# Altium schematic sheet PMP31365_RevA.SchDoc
size A2; Date: Not shown in title block; ApprovedBy: Not shown in title block; CheckedBy: Not shown in title block; Author: Not shown in title block; CompanyName: Not shown in title block; Engineer: Not shown in title block; Organization: Not shown in title block; Address1: Not shown in title block; Address2: Not shown in title block; Address3: Not shown in title block; Address4: Not shown in title block; DocumentNumber: 2; Revision: Use project parameter SCH_Rev; SheetNumber: 1; SheetTotal: 1; PageSetup: Record=PageOptions¦CenterHorizontal=True¦CenterVertical=True¦PrintScale=1.00¦XCorrection=1.00¦YCorrection=1.00¦PrintKind=0¦BorderSize=5000000¦LeftOffset=0¦BottomOffset=0¦Orientation=2¦PaperLength=1000¦PaperWidth=1000¦Scale=100¦PaperSource=15¦PrintQuality=600¦MediaType=1¦DitherType=10¦PaperKind=Letter¦PrintScaleMode=1
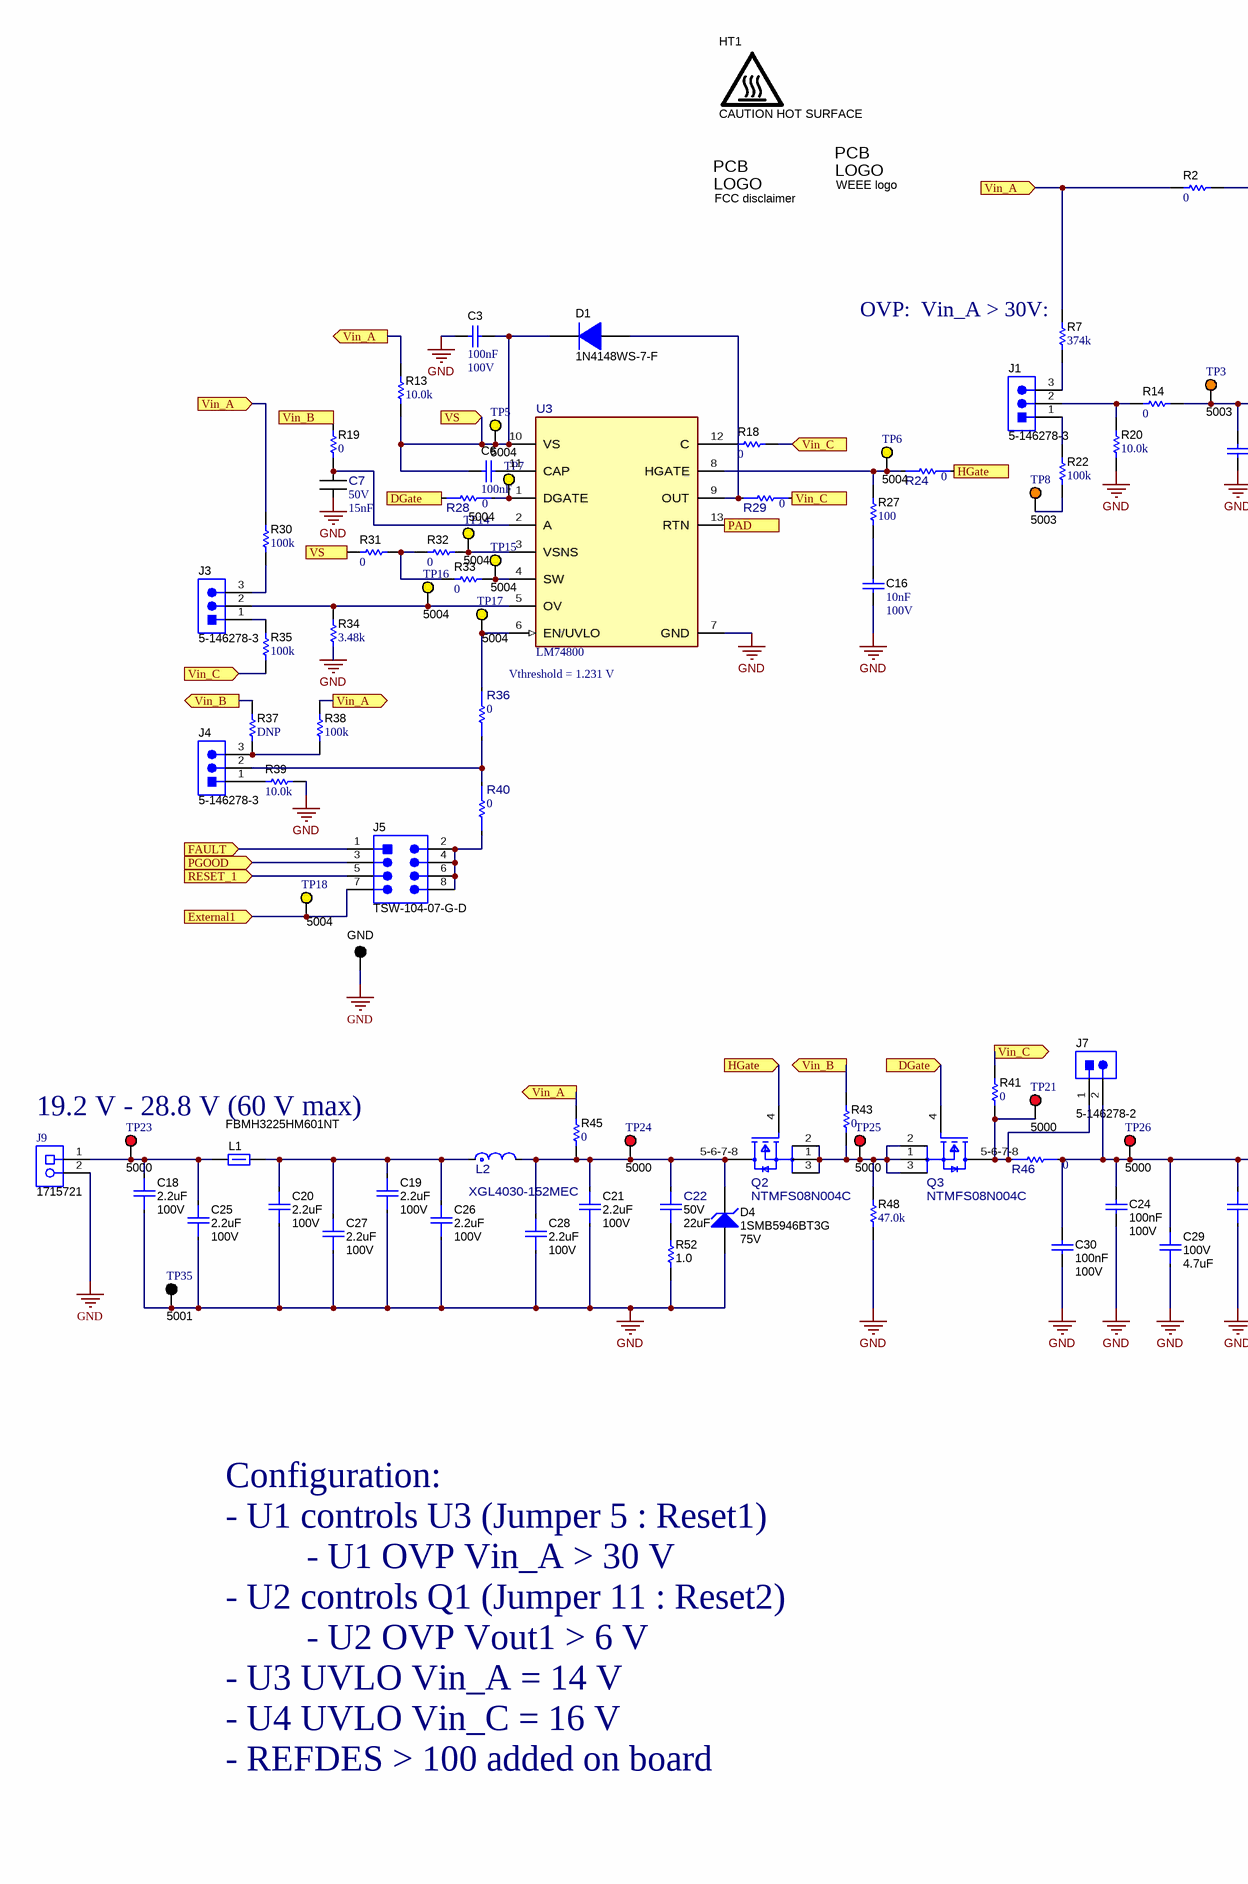
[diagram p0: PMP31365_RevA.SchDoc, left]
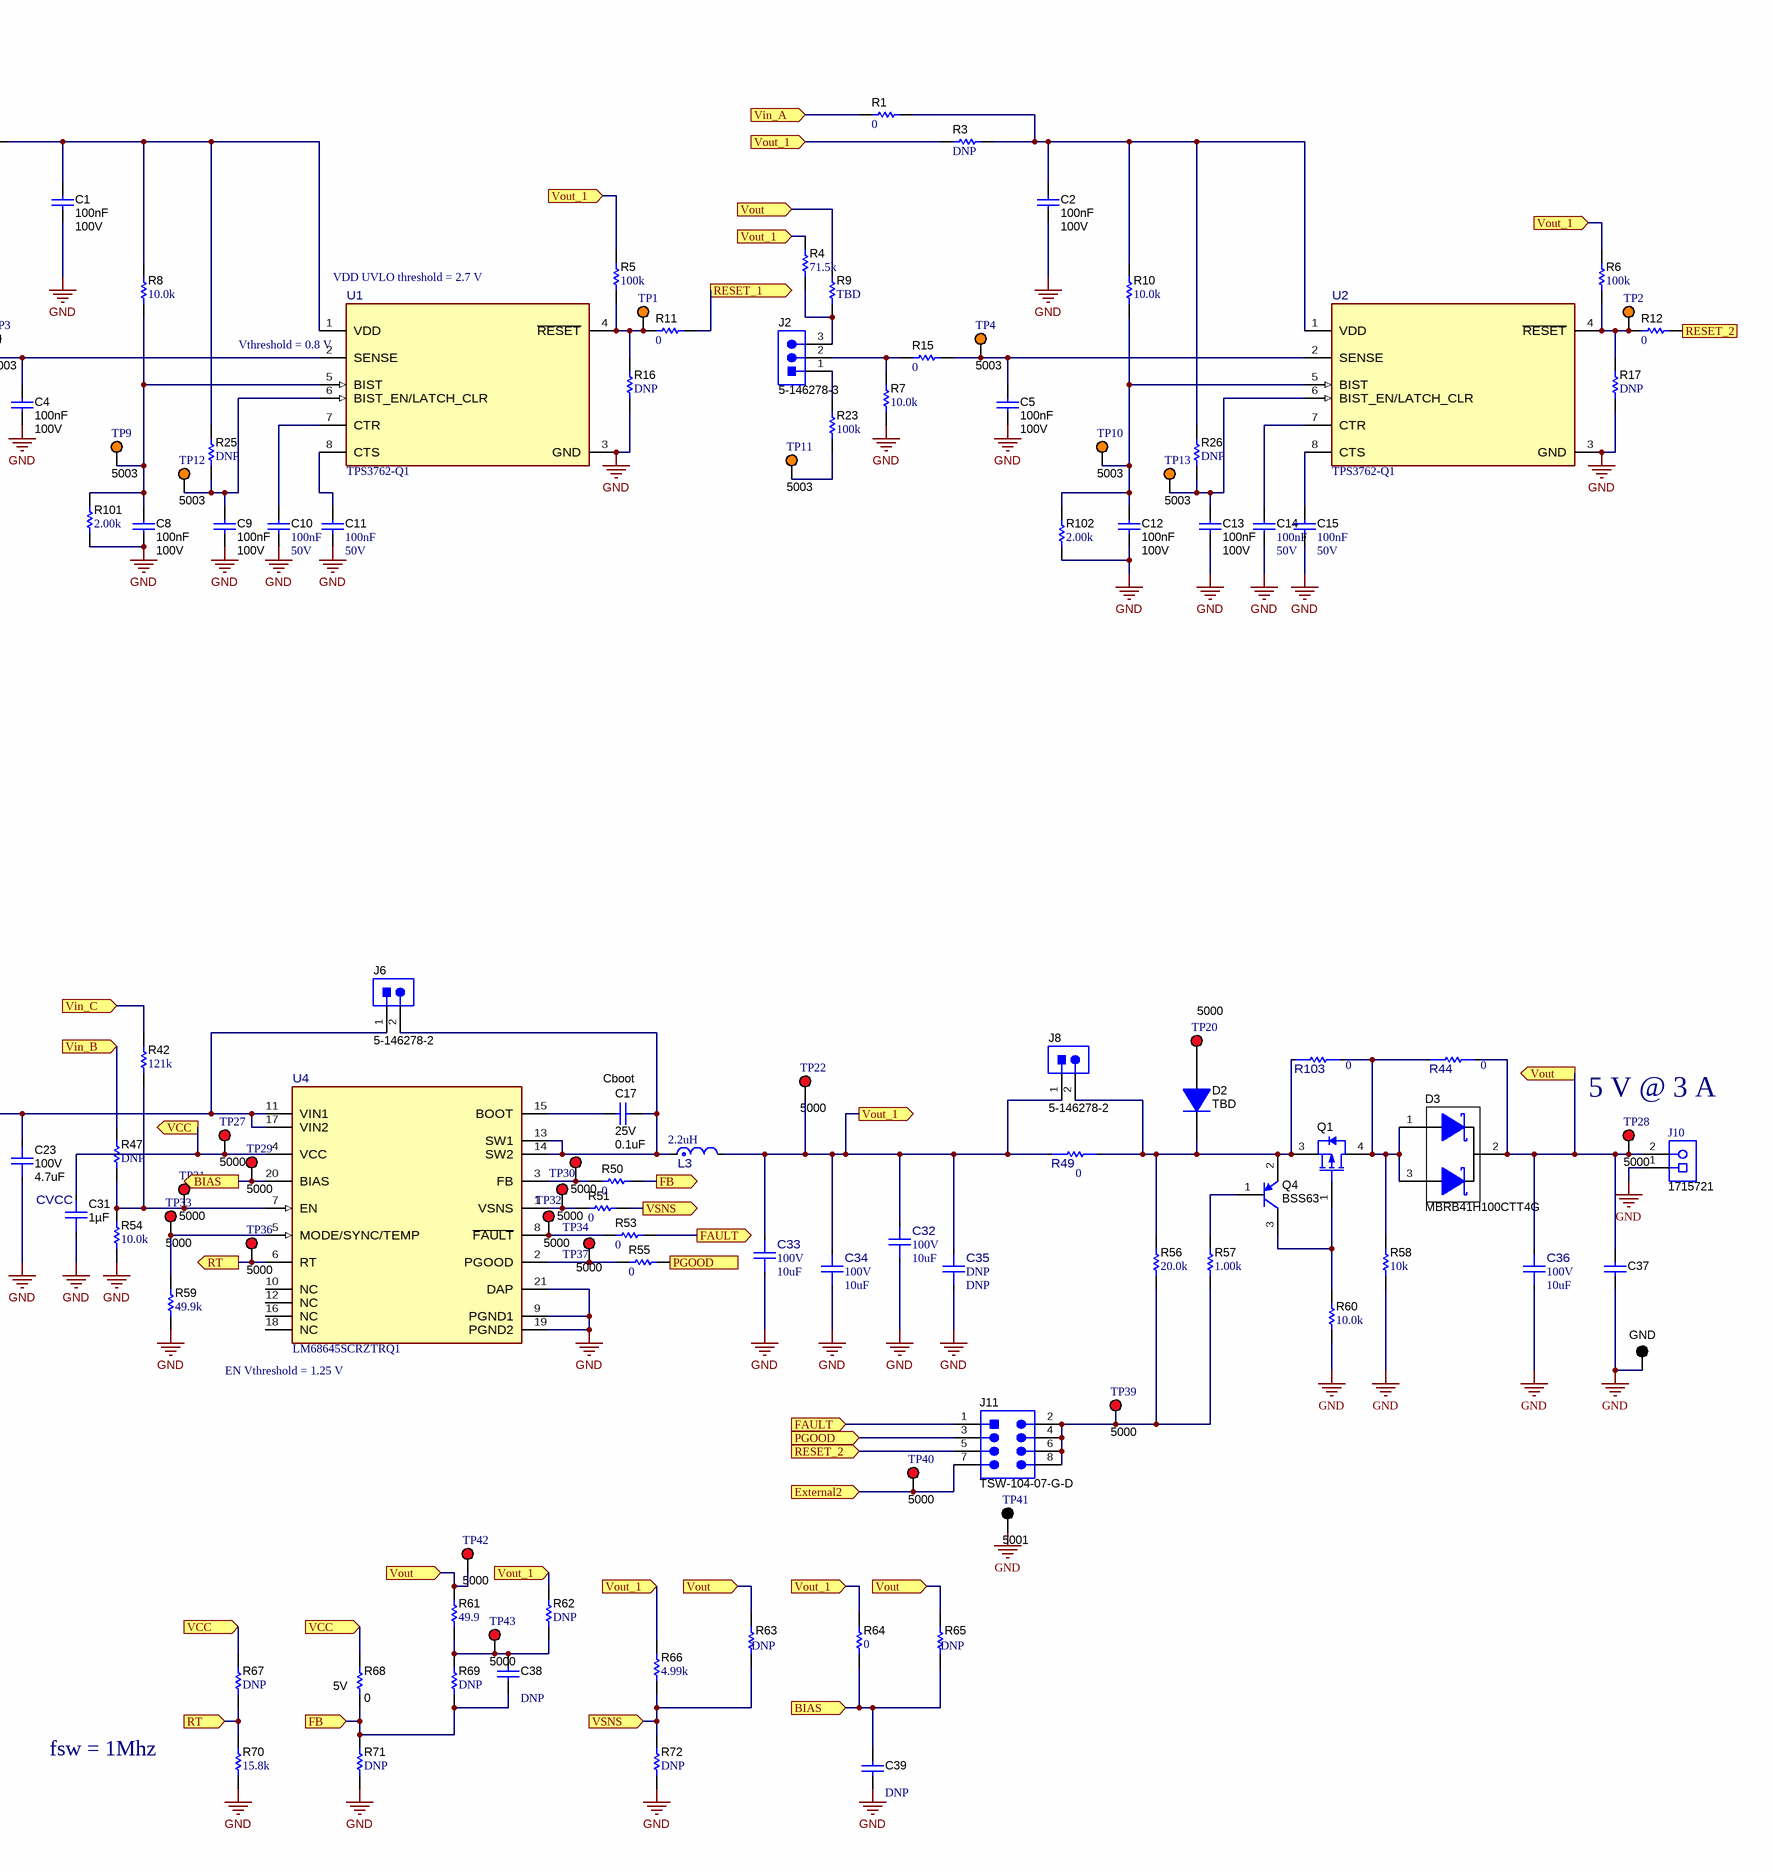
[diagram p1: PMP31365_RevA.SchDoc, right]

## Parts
(Parts that share a designator on the sheet are numbered #1, #2 ... from top to bottom, then left to right.)
1  FCC disclaimer  [FCC_disclaimer]  (no BOM)
C1  Cap_F: 100nF  VDC_V: 100V  [0603L]  (hidden comment: HMK107B7104KAHT)
C2  Cap_F: 100nF  VDC_V: 100V  [0603L]  (hidden comment: HMK107B7104KAHT)
C3  Cap_F: 100nF  VDC_V: 100V  [0603]  (hidden comment: GRM188R72A104KA35D)
C4  Cap_F: 100nF  VDC_V: 100V  [0603L]  (hidden comment: HMK107B7104KAHT)
C5  Cap_F: 100nF  VDC_V: 100V  [0603L]  (hidden comment: HMK107B7104KAHT)
C6  Cap_F: 100nF  [0603]  (hidden comment: 06035C104KAZ2A)
C7  VDC_V: 50V  Cap_F: 15nF  [FP-C0603C153K5RACTU_0603-MFG]  (hidden comment: C0603C153K5RACTU)
C8  Cap_F: 100nF  VDC_V: 100V  [0603L]  (hidden comment: HMK107B7104KAHT)
C9  Cap_F: 100nF  VDC_V: 100V  [0603L]  (hidden comment: HMK107B7104KAHT)
C10  Cap_F: 100nF  VDC_V: 50V  [0603]  (hidden comment: C0603C104K5RACTU)
C11  Cap_F: 100nF  VDC_V: 50V  [0603]  (hidden comment: C0603C104K5RACTU)
C12  Cap_F: 100nF  VDC_V: 100V  [0603L]  (hidden comment: HMK107B7104KAHT)
C13  Cap_F: 100nF  VDC_V: 100V  [0603L]  (hidden comment: HMK107B7104KAHT)
C14  Cap_F: 100nF  VDC_V: 50V  [0603]  (hidden comment: C0603C104K5RACTU)
C15  Cap_F: 100nF  VDC_V: 50V  [0603]  (hidden comment: C0603C104K5RACTU)
C16  Cap_F: 10nF  VDC_V: 100V  [0805_HV]  (hidden comment: 08051C103JAT2A)
C17  Cboot  VDC_V: 25V  ValueDisplayed: 0.1uF  [0402L]
C18  ValueDisplayed: 2.2uF  VDC_V: 100V  [FP-GRM21BD72A225ME01K_0805-IPC_C]  (hidden comment: GRM21BD72A225ME01K)
C19  ValueDisplayed: 2.2uF  VDC_V: 100V  [FP-GRM21BD72A225ME01K_0805-IPC_C]  (hidden comment: GRM21BD72A225ME01K)
C20  ValueDisplayed: 2.2uF  VDC_V: 100V  [FP-GRM21BD72A225ME01K_0805-IPC_C]  (hidden comment: GRM21BD72A225ME01K)
C21  ValueDisplayed: 2.2uF  VDC_V: 100V  [FP-GRM21BD72A225ME01K_0805-IPC_C]  (hidden comment: GRM21BD72A225ME01K)
C22  VDC_V: 50V  ValueDisplayed: 22uF  [FP-CGA9P3X7R1H226M250KB_2220-MFG]  (hidden comment: CGA9P3X7R1H226M250KB)
C23  VDC_V: 100V  ValueDisplayed: 4.7uF  [FP-GRM31CC72A475KE11L_1206-IPC_C]  (hidden comment: GRM31CC72A475KE11L)
C24  Cap_F: 100nF  VDC_V: 100V  [0603L]  (hidden comment: HMK107B7104KAHT)
C25  ValueDisplayed: 2.2uF  VDC_V: 100V  [FP-GRM21BD72A225ME01K_0805-IPC_C]  (hidden comment: GRM21BD72A225ME01K)
C26  ValueDisplayed: 2.2uF  VDC_V: 100V  [FP-GRM21BD72A225ME01K_0805-IPC_C]  (hidden comment: GRM21BD72A225ME01K)
C27  ValueDisplayed: 2.2uF  VDC_V: 100V  [FP-GRM21BD72A225ME01K_0805-IPC_C]  (hidden comment: GRM21BD72A225ME01K)
C28  ValueDisplayed: 2.2uF  VDC_V: 100V  [FP-GRM21BD72A225ME01K_0805-IPC_C]  (hidden comment: GRM21BD72A225ME01K)
C29  VDC_V: 100V  ValueDisplayed: 4.7uF  [FP-GRM31CC72A475KE11L_1206-IPC_C]  (hidden comment: GRM31CC72A475KE11L)
C30  Cap_F: 100nF  VDC_V: 100V  [0603L]  (hidden comment: HMK107B7104KAHT)
C31  CVCC  Cap_F: 1µF  [FP-CGA3E1X7R1C105M080AC_0603-IPC_C]
C32  VDC_V: 100V  ValueDisplayed: 10uF  [FP-C3225X7R2A106K250AC_1210-MFG]  (hidden comment: C3225X7R2A106K250AC)
C33  VDC_V: 100V  ValueDisplayed: 10uF  [FP-C3225X7R2A106K250AC_1210-MFG]  (hidden comment: C3225X7R2A106K250AC)
C34  VDC_V: 100V  ValueDisplayed: 10uF  [FP-C3225X7R2A106K250AC_1210-MFG]  (hidden comment: C3225X7R2A106K250AC)
C35  C3225X7R2A106K250AC  [FP-C3225X7R2A106K250AC_1210-MFG]  (value not drawn)
C36  VDC_V: 100V  ValueDisplayed: 10uF  [FP-C3225X7R2A106K250AC_1210-MFG]  (hidden comment: C3225X7R2A106K250AC)
C37  Used in BOM report  [1210]  (value not drawn)
C38  C0603C100J5GACTU  [0603]  (value not drawn)
C39  C0603C100J5GACTU  [0603]  (value not drawn)
D1  1N4148WS-7-F  [SOD-323]
D2  TBD  [SMA]
D3  MBRB41H100CTT4G  [DDPAK]
D4  1SMB5946BT3G  value 75V  [SMB]
HT1  CAUTION HOT SURFACE  [IEC_HotSurface_Medium]  (no BOM)
J1  5-146278-3  [TE_5-146278-3]
J2  5-146278-3  [TE_5-146278-3]
J3  5-146278-3  [TE_5-146278-3]
J4  5-146278-3  [TE_5-146278-3]
J5  TSW-104-07-G-D  [TSW-104-07-G-D]
J6  5-146278-2  [TE_5-146278-2]
J7  5-146278-2  [TE_5-146278-2]
J8  5-146278-2  [TE_5-146278-2]
J9  1715721  [PhoenixContact_1715721]
J10  1715721  [PhoenixContact_1715721]
J11  TSW-104-07-G-D  [TSW-104-07-G-D]
L1  FBMH3225HM601NT  [1210_280]
L2  XGL4030-152MEC  [FP-XGL4030-152MEC_SMT2_4MM0_4MM0-MFG]
L3  value 2.2uH  [FP-XGL6060-182MEC_SMT2_6MM51_6MM71-MFG]  (hidden comment: XGL6060-222MEC)
Q1  (no value)  [DPAK]
Q2  NTMFS08N004C  [FP-NTMFS08N004C_PQFN8-MFG]
Q3  NTMFS08N004C  [FP-NTMFS08N004C_PQFN8-MFG]
Q4  BSS63  [SOT-23]
R1  ValueDisplayed: 0  [0603]  (hidden comment: RMCF0603ZT0R00)
R2  ValueDisplayed: 0  [0603]  (hidden comment: RMCF0603ZT0R00)
R3  RMCF0603ZT0R00  [0603]  (value not drawn)
R4  ValueDisplayed: 71.5k  [0603]  (hidden comment: CRCW060371K5FKEA)
R5  ValueDisplayed: 100k  [0603]  (hidden comment: CRCW0603100KFKEA)
R6  ValueDisplayed: 100k  [0603]  (hidden comment: CRCW0603100KFKEA)
R7#1  ValueDisplayed: 374k  [0603]  (hidden comment: CRCW0603374KFKEA)
R7#2  ValueDisplayed: 10.0k  [0603]  (hidden comment: CRCW060310K0FKEA)
R8  ValueDisplayed: 10.0k  [0603]  (hidden comment: CRCW060310K0FKEA)
R9  ValueDisplayed: TBD  [0603]  (hidden comment: RMCF0603ZT0R00)
R10  ValueDisplayed: 10.0k  [0603]  (hidden comment: CRCW060310K0FKEA)
R11  ValueDisplayed: 0  [0603]  (hidden comment: RMCF0603ZT0R00)
R12  ValueDisplayed: 0  [0603]  (hidden comment: RMCF0603ZT0R00)
R13  ValueDisplayed: 10.0k  [0603]  (hidden comment: CRCW060310K0FKEA)
R14  ValueDisplayed: 0  [0603]  (hidden comment: RMCF0603ZT0R00)
R15  ValueDisplayed: 0  [0603]  (hidden comment: RMCF0603ZT0R00)
R16  RMCF0603ZT0R00  [0603]  (value not drawn)
R17  RMCF0603ZT0R00  [0603]  (value not drawn)
R18  ValueDisplayed: 0  [0603]  (hidden comment: RMCF0603ZT0R00)
R19  ValueDisplayed: 0  [0603]  (hidden comment: RMCF0603ZT0R00)
R20  ValueDisplayed: 10.0k  [0603]  (hidden comment: CRCW060310K0FKEA)
R22  ValueDisplayed: 100k  [0603]  (hidden comment: CRCW0603100KFKEA)
R23  ValueDisplayed: 100k  [0603]  (hidden comment: CRCW0603100KFKEA)
R24  Res_ohm: 0  [FP-RMCF0805ZT0R00_0805-MFG]  (hidden comment: RMCF0805ZT0R00)
R25  DNP  [0603]
R26  DNP  [0603]
R27  ValueDisplayed: 100  [0805_HV]  (hidden comment: CRCW0805100RFKEA)
R28  Res_ohm: 0  [FP-RMCF0805ZT0R00_0805-MFG]  (hidden comment: RMCF0805ZT0R00)
R29  Res_ohm: 0  [FP-RMCF0805ZT0R00_0805-MFG]  (hidden comment: RMCF0805ZT0R00)
R30  ValueDisplayed: 100k  [0603]  (hidden comment: CRCW0603100KFKEA)
R31  ValueDisplayed: 0  [0603]  (hidden comment: RMCF0603ZT0R00)
R32  ValueDisplayed: 0  [0603]  (hidden comment: RMCF0603ZT0R00)
R33  ValueDisplayed: 0  [0603]  (hidden comment: RMCF0603ZT0R00)
R34  ValueDisplayed: 3.48k  [0603]  (hidden comment: CRCW06033K48FKEA)
R35  ValueDisplayed: 100k  [0603]  (hidden comment: CRCW0603100KFKEA)
R36  Res_ohm: 0  [FP-RMCF0805ZT0R00_0805-MFG]  (hidden comment: RMCF0805ZT0R00)
R37  DNP  [0603]
R38  ValueDisplayed: 100k  [0603]  (hidden comment: CRCW0603100KFKEA)
R39  ValueDisplayed: 10.0k  [0603]  (hidden comment: CRCW060310K0FKEA)
R40  Res_ohm: 0  [FP-RMCF0805ZT0R00_0805-MFG]  (hidden comment: RMCF0805ZT0R00)
R41  ValueDisplayed: 0  [0603]  (hidden comment: RMCF0603ZT0R00)
R42  ValueDisplayed: 121k  [0603]  (hidden comment: CRCW0603121KFKEA)
R43  ValueDisplayed: 0  [0603]  (hidden comment: RMCF0603ZT0R00)
R44  value 0  [FP-CRCW12060000Z0EAC_1206-MFG]  (hidden comment: CRCW12060000Z0EAC)
R45  ValueDisplayed: 0  [0603]  (hidden comment: RMCF0603ZT0R00)
R46  value 0  [FP-CRCW12060000Z0EAC_1206-MFG]  (hidden comment: CRCW12060000Z0EAC)
R47  RMCF0603ZT0R00  [0603]  (value not drawn)
R48  ValueDisplayed: 47.0k  [1206]  (hidden comment: RC1206FR-0747KL)
R49  value 0  [FP-CRCW12060000Z0EAC_1206-MFG]  (hidden comment: CRCW12060000Z0EAC)
R50  ValueDisplayed: 0  [0603]  (hidden comment: RMCF0603ZT0R00)
R51  ValueDisplayed: 0  [0603]  (hidden comment: RMCF0603ZT0R00)
R52  ValueDisplayed: 1.0  [0805_HV]  (hidden comment: ESR10EZPJ1R0)
R53  ValueDisplayed: 0  [0603]  (hidden comment: RMCF0603ZT0R00)
R54  ValueDisplayed: 10.0k  [0603]  (hidden comment: CRCW060310K0FKEA)
R55  ValueDisplayed: 0  [0603]  (hidden comment: RMCF0603ZT0R00)
R56  ValueDisplayed: 20.0k  [0603]  (hidden comment: CRCW060320K0FKEA)
R57  ValueDisplayed: 1.00k  [0603]  (hidden comment: CRCW06031K00FKEA)
R58  ValueDisplayed: 10k  [1206]  (hidden comment: CRCW120610K0JNEA)
R59  ValueDisplayed: 49.9k  [0603]  (hidden comment: CRCW060349K9FKEA)
R60  ValueDisplayed: 10.0k  [0603]  (hidden comment: CRCW060310K0FKEA)
R61  ValueDisplayed: 49.9  [0603]  (hidden comment: M55342K12B49D9T)
R62  RMCF0603ZT0R00  [0603]  (value not drawn)
R63  RMCF0603ZT0R00  [0603]  (value not drawn)
R64  ValueDisplayed: 0  [0603]  (hidden comment: RMCF0603ZT0R00)
R65  RMCF0603ZT0R00  [0603]  (value not drawn)
R66  ValueDisplayed: 4.99k  [0603]  (hidden comment: CRCW06034K99FKEA)
R67  RMCF0603ZT0R00  [0603]  (value not drawn)
R68  5V  ValueDisplayed: 0  [0603L]
R69  RMCF0603ZT0R00  [0603]  (value not drawn)
R70  ValueDisplayed: 15.8k  [0603]  (hidden comment: CRCW060315K8FKEA)
R71  RMCF0603ZT0R00  [0603]  (value not drawn)
R72  RMCF0603ZT0R00  [0603]  (value not drawn)
R101  ValueDisplayed: 2.00k  [VSMP_0603]  (hidden comment: Y16362K00000F9R)
R102  ValueDisplayed: 2.00k  [VSMP_0603]  (hidden comment: Y16362K00000F9R)
R103  value 0  [FP-CRCW12060000Z0EAC_1206-MFG]  (hidden comment: CRCW12060000Z0EAC)
TP1  5003  [Keystone5003]  (value not drawn)
TP2  5003  [Keystone5003]  (value not drawn)
TP3  5003  [Keystone5003]
TP4  5003  [Keystone5003]
TP5  5004  [Keystone5004]
TP6  5004  [Keystone5004]
TP7  5004  [Keystone5004]
TP8  5003  [Keystone5003]
TP9  5003  [Keystone5003]
TP10  5003  [Keystone5003]
TP11  5003  [Keystone5003]
TP12  5003  [Keystone5003]
TP13  5003  [Keystone5003]
TP14  5004  [Keystone5004]
TP15  5004  [Keystone5004]
TP16  5004  [Keystone5004]
TP17  5004  [Keystone5004]
TP18  5004  [Keystone5004]
TP19  GND  [Keystone5011]
TP20  5000  [Keystone5000]
TP21  5000  [Keystone5000]
TP22  5000  [Keystone5000]
TP23  5000  [Keystone5000]
TP24  5000  [Keystone5000]
TP25  5000  [Keystone5000]
TP26  5000  [Keystone5000]
TP27  5000  [Keystone5000]
TP28  5000  [Keystone5000]
TP29  5000  [Keystone5000]
TP30  5000  [Keystone5000]
TP31  5000  [Keystone5000]
TP32  5000  [Keystone5000]
TP33  5000  [Keystone5000]
TP34  5000  [Keystone5000]
TP35  5001  [Keystone5001]
TP36  5000  [Keystone5000]
TP37  5000  [Keystone5000]
TP38  GND  [Keystone5011]
TP39  5000  [Keystone5000]
TP40  5000  [Keystone5000]
TP41  5001  [Keystone5001]
TP42  5000  [Keystone5000]
TP43  5000  [Keystone5000]
U1  TPS3762-Q1  [DDF0008A-MFG]
U2  TPS3762-Q1  [DDF0008A-MFG]
U3  LM74800  [DRR0012E-MFG]
U4  LM68645SCRZTRQ1  [RZT0020A-MFG]
x1  WEEE logo  [WEEE_Minimum]  (no BOM)

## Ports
BIAS (in), BIAS (out), DGate (in), DGate (out), External1 (in), External2 (in), FAULT (in), FAULT (out), FB (in), FB (out), HGate (in), HGate (out), PAD (out), PGOOD (in), PGOOD (out), RESET_1 (in), RESET_1 (out), RESET_2 (in), RESET_2 (out), RT (in), RT (out), VCC (in), VCC (out), Vin_A (in), Vin_A (out), Vin_B (in), Vin_B (out), Vin_C (in), Vin_C (out), Vout (in), Vout (out), Vout_1 (in), Vout_1 (out), VS (in), VSNS (in), VSNS (out)

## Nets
GND: C1.2 C2.2 C3.2 C4.2 C5.2 C7.2 C8.2 C9.2 C10.2 C11.2 C12.2 C13.2 C14.2 C15.2 C16.2 C18.1 C19.1 C20.1 C21.1 C23.1 C24.2 C25.1 C26.1 C27.1 C28.1 C29.1 C30.2 C31.1 C32.1 C33.1 C34.1 C35.1 C36.1 C37.2 C39.2 D4.2(A) J9.2 J10.1 R7#2.1 R16.1 R17.1 R20.1 R34.1 R39.1 R48.1 R52.1 R54.1 R58.1 R59.1 R60.1 R70.1 R71.1 R72.1 R101.1 R102.1 TP19.1 TP35.1 TP38.1 TP41.1 U1.3(GND) U2.3(GND) U3.7(GND) U4.9(PGND1) U4.19(PGND2) U4.21(DAP)
BIAS: C39.1 R64.2 R65.1 TP29.1 U4.20(BIAS) ; port BIAS
DGate: Q3.4(G) R28.2 ; port DGate
External1: J5.7 TP18.1 ; port External1
External2: J11.7 TP40.1 ; port External2
FAULT: J5.1 J11.1 R53.1 ; port FAULT
FB: C38.2 R50.1 R68.2 R69.1 R71.2 ; port FB
HGate: Q2.4(G) R24.1 ; port HGate
PAD: U3.13(RTN) ; port PAD
PGOOD: J5.3 J11.3 R55.1 ; port PGOOD
RESET_1: J5.5 R11.1 ; port RESET_1
RESET_2: J11.5 R12.1 ; port RESET_2
RT: R67.1 R70.2 TP36.1 U4.6(RT) ; port RT
VCC: C31.2 R67.2 R68.1 TP27.1 U4.4(VCC) ; port VCC
Vin_A: R1.1 R2.1 R7#1.2 R13.2 R30.1 R38.1 R45.2 ; port Vin_A
Vin_B: R19.2 R37.2 R43.2 R47.2 ; port Vin_B
Vin_C: R18.2 R29.1 R35.2 R41.2 R42.2 ; port Vin_C
Vout: C36.2 C37.1 D3.2(K) J10.2 R9.1 R44.2 R61.2 R63.2 R65.2 TP28.1 TP42.1 ; port Vout
Vout_1: C32.2 C33.2 C34.2 C35.2 J8.1 L3.2 R3.2 R4.2 R5.1 R6.1 R49.1 R62.2 R64.1 R66.2 TP22.1 ; port Vout_1
VS: C3.1 C6.1 D1.1(K) R13.1 R31.1 TP5.1 U3.10(VS) ; port VS
VSNS: R51.1 R63.1 R66.1 R72.2 ; port VSNS
NetC1_1: C1.1 R2.2 R8.2 R25.2 U1.1(VDD)
NetC2_1: C2.1 R1.2 R3.1 R10.2 R26.2 U2.1(VDD)
NetC4_1: C4.1 R14.1 TP3.1 U1.2(SENSE)
NetC5_1: C5.1 R15.1 TP4.1 U2.2(SENSE)
NetC6_2: C6.2 U3.11(CAP)
NetC7_1: C7.1 R19.1 U3.2(A)
NetC8_1: C8.1 R8.1 R101.2 TP9.1 U1.5(BIST)
NetC9_1: C9.1 R25.1 TP12.1 U1.6(BIST_EN/LATCH_CLR)
NetC10_1: C10.1 U1.7(CTR)
NetC11_1: C11.1 U1.8(CTS)
NetC12_1: C12.1 R10.1 R102.2 TP10.1 U2.5(BIST)
NetC13_1: C13.1 R26.1 TP13.1 U2.6(BIST_EN/LATCH_CLR)
NetC14_1: C14.1 U2.7(CTR)
NetC15_1: C15.1 U2.8(CTS)
NetC16_1: C16.1 R27.1
NetC17_1: C17.1 J6.2 L3.1 U4.13(SW1) U4.14(SW2)
NetC17_2: C17.2 U4.15(BOOT)
NetC18_2: C18.2 C25.2 J9.1 L1.1 TP23.1
NetC19_2: C19.2 C20.2 C26.2 C27.2 L1.2 L2.1
NetC21_2: C21.2 C22.2 C28.2 D4.1(K) L2.2 Q2.5-6-7-8(D) R45.1 TP24.1
NetC22_1: C22.1 R52.2
NetC23_2: C23.2 C24.1 C29.2 C30.1 J6.1 J7.2 R46.2 TP26.1 U4.11(VIN1) U4.17(VIN2)
NetC38_1: C38.1 R61.1 R62.1 R69.2 TP43.1
NetD1_2: D1.2(A) R29.2 U3.9(OUT)
NetD2_1: D2.1(K) J8.2 Q1.3(S) Q4.2(E) R49.2 R56.2 R103.1
NetD2_2: D2.2(A) TP20.1
NetD3_1: D3.1(A) D3.3(A) Q1.4(D) R44.1 R58.2 R103.2
NetJ1_1: J1.1 R22.1
NetJ1_2: J1.2 R14.2 R20.2
NetJ1_3: J1.3 R7#1.1
NetJ2_1: J2.1 R23.1
NetJ2_2: J2.2 R7#2.2 R15.2
NetJ2_3: J2.3 R4.1 R9.2
NetJ3_1: J3.1 R35.1
NetJ3_2: J3.2 R34.2 TP16.1 U3.5(OV)
NetJ3_3: J3.3 R30.2
NetJ4_1: J4.1 R39.2
NetJ4_2: J4.2 R36.2 R40.1
NetJ4_3: J4.3 R37.1 R38.2
NetJ5_2: J5.2 J5.4 J5.6 J5.8 R40.2
NetJ7_1: J7.1 Q3.5-6-7-8(D) R41.1 R46.1 TP21.1
NetJ11_2: J11.2 J11.4 J11.6 J11.8 R56.1 R57.1 TP39.1
NetQ1_1: Q1.1(G) Q4.3(C) R60.2
NetQ2_1: Q2.1(S) Q2.2(S) Q2.3(S) Q3.1(S) Q3.2(S) Q3.3(S) R43.1 R48.2 TP25.1
NetQ4_1: Q4.1(B) R57.2
NetR5_2: R5.2 R11.2 R16.2 TP1.1 U1.4(~{RESET})
NetR6_2: R6.2 R12.2 R17.2 TP2.1 U2.4(~{RESET})
NetR18_1: R18.1 U3.12(C)
NetR22_2: R22.2 TP8.1
NetR23_2: R23.2 TP11.1
NetR24_2: R24.2 R27.2 TP6.1 U3.8(HGATE)
NetR28_1: R28.1 TP7.1 U3.1(DGATE)
NetR31_2: R31.2 R32.1 R33.1
NetR32_2: R32.2 TP14.1 U3.3(VSNS)
NetR33_2: R33.2 TP15.1 U3.4(SW)
NetR36_1: R36.1 TP17.1 U3.6(EN/UVLO)
NetR42_1: R42.1 R47.1 R54.2 TP31.1 U4.7(EN)
NetR50_2: R50.2 TP30.1 U4.3(FB)
NetR51_2: R51.2 TP32.1 U4.1(VSNS)
NetR53_2: R53.2 TP34.1 U4.8(~{FAULT})
NetR55_2: R55.2 TP37.1 U4.2(PGOOD)
NetR59_2: R59.2 TP33.1 U4.5(MODE/SYNC/TEMP)

Not connected (* = marked no-connect by the designer): U4 10(NC) 12(NC) 16(NC) 18(NC)

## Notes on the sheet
- (near R7#1) OVP:  Vin_A > 30V:
- (near U1) VDD UVLO threshold = 2.7 V
- (near U1) Vthreshold = 0.8 V
- Vthreshold = 1.231 V
- 19.2 V - 28.8 V (60 V max)
- 5 V @ 3 A
- (near U4) EN Vthreshold = 1.25 V
- Configuration:
- - U1 controls U3 (Jumper 5 : Reset1)
- - U1 OVP Vin_A > 30 V
- - U2 controls Q1 (Jumper 11 : Reset2)
- - U3 UVLO Vin_A = 14 V
- - U2 OVP Vout1 > 6 V
- - U4 UVLO Vin_C = 16 V
- - REFDES > 100 added on board
- fsw = 1Mhz

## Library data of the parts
1 = CMP-0074847-1: FCC_disclaimer; Library Reference: Logo
C1 C2 C4 C5 C8 C9 C12 C13 C24 C30 = CMP-0081011-1: CAP, CERM, 0.1 µF, 100 V,+/- 10%, X7R, AEC-Q200 Grade 1, 0603; Manufacturer: Taiyo Yuden; SizeAreaWB_mm2: 4.68; SizeArea_mm2: 1.28; AEC Qualified: Y; AEC Category: Q200; Value: 0.1uF; TaMax_C: 125°C; SizeZ_mm: 1; Polarized: N; TaMin_C: -55°C; SizeY_mm: 0.8; U/M: EA; CompType: Capacitor; SizeX_mm: 1.6; Cap_Case: 0603; ValueDisplayed: 0.1µF
C3 = CMP-0007469-4: CAP, CERM, 0.1 uF, 100 V, +/- 10%, X7R, 0603; Manufacturer: MuRata; TaMin_C: -55°C; Polarized: N; SizeAreaWB_mm2: 4.68; Value1: Unknown; U/M: EA; Value: 0.1uF; TaMax_C: 125°C; SizeZ_mm: 1; SizeX_mm: 1.6; SizeY_mm: 0.8; SizeArea_mm2: 1.28; AEC Category: Q200
C6 = CMP-0079095-1: CAP, CERM, 0.1 µF, 50 V,+/- 10%, X7R, AEC-Q200 Grade 1, 0603; Manufacturer: AVX; SizeAreaWB_mm2: 4.68; SizeArea_mm2: 1.28; AEC Qualified: Y; AEC Category: Q200; Value: 0.1uF; TaMax_C: 125°C; SizeZ_mm: 1; Polarized: N; TaMin_C: -55°C; VDC_V: 50V; SizeY_mm: 0.8; U/M: EA; SizeX_mm: 1.6; ValueDisplayed: 0.1µF
C7 = CMP-0086419-1: Cap Ceramic 0.015uF 50V X7R 10% Pad SMD 0603 125°C T/R; Manufacturer: Kemet; Symbol Name: SYM-C0603C153K5RACTU; TempCo: 15%; SizeZ_mm: 0.87mm; AEC Qualified: No
C10 C11 C14 C15 = CMP-0006861-3: CAP, CERM, 0.1 uF, 50 V, +/- 10%, X7R, 0603; Manufacturer: Kemet; TaMin_C: -55°C; Polarized: N; SizeAreaWB_mm2: 4.68; Value1: Unknown; U/M: EA; Value: 0.1uF; TaMax_C: 125°C; SizeZ_mm: 1; SizeX_mm: 1.6; SizeY_mm: 0.8; SizeArea_mm2: 1.28; AEC Category: Q200
C16 = CMP-0007542-1: CAP, CERM, 0.01 uF, 100 V, +/- 5%, X7R, 0805; Manufacturer: AVX; TaMin_C: -55°C; ESR_ohm: 78m; Polarized: N; SizeAreaWB_mm2: 6.75; Value1: 0.078 ohm; U/M: EA; Value: 0.01uF; TaMax_C: 125°C; SizeZ_mm: 1.45; SizeX_mm: 2; SizeY_mm: 1.25; Cap_Case: 0805; SizeArea_mm2: 2.5; AEC Category: Q200
C17 = CMP-0006295-2: CAP, CERM, 0.1 uF, 25 V, +/- 20%, X7R, 0402; Manufacturer: TDK; PartNumber: C1005X7R1E104M050BB; TaMin_C: -55°C; Polarized: N; SizeAreaWB_mm2: 3; Value1: Unknown; U/M: EA; Value: 0.1uF; TaMax_C: 125°C; SizeZ_mm: 0.6; SizeX_mm: 1; SizeY_mm: 0.5; Cap_Case: 0402; CompType: Capacitor; Cap_F: 100nF; AEC Category: Q200
C18-C21 C25-C28 = CMP-0096278-1: Chip Multilayer Ceramic Capacitor for General Purpose 2.2uF ±20% 100V X7T SMD 0805; Manufacturer: Murata; AEC Qualified: No; Cap_F: 2.2µF; Value: 2.2µF; SizeZ_mm: 1.45mm; TempCo: +22/-33%
C22 = CMP-0097369-1: Cap Ceramic 22uF 50V X7R 20% SMD 2220 125°C T/R; Manufacturer: TDK; AEC Grade: Grade 1; SizeZ_mm: 2.8mm; AEC Qualified: Yes; Value: 22µF; TempCo: 15%
C23 C29 = CMP-0089881-1: 4.7µF ±10% 100V Ceramic Capacitor X7S 1206 (3216 Metric); Manufacturer: Murata; TempCo: 22%; AEC Qualified: No; SizeZ_mm: 1.9mm
C31 = CMP-0095369-1: Cap Ceramic 1uF 16V X7R 20% Pad SMD 0603 +125°C Automotive T/R; PartNumber: CGA3E1X7R1C105M080AC; Manufacturer: TDK; AEC Qualified: Yes; Tolerance_%: 0.2%; SizeZ_mm: 1.1mm; Value: 1µF; TempCo: 0.15; AEC Grade: Grade 1
C32-C34 C36 = CMP-0096021-1: 10 µF ±10% 100V Ceramic Capacitor X7R 1210 (3225 Metric); Manufacturer: TDK; Cap_F: 10µF; AEC Qualified: No; Value: 10µF; SizeZ_mm: 2.85mm; TempCo: 15%
C35 = CMP-0096021-1: DNP; Manufacturer: TDK; AEC Qualified: No; Tolerance_%: 10%; SizeZ_mm: 2.85mm; Temperature Characteristic: X7R; TempCo: 15%
C37 = Capacitor: CAP, CERM, xxxF, xxV, [TempCo], xx%, [PackageReference]; Polarized: N; U/M: EA
C38 C39 = CMP-0006839-2: DNP; Manufacturer: Kemet; TaMin_C: -55°C; Polarized: N; TempCo: C0G/NP0; SizeAreaWB_mm2: 4.68; Value1: Unknown; U/M: EA; Value: 10pF; TaMax_C: 125°C; Tolerance_%: 5%; SizeZ_mm: 1; SizeX_mm: 1.6; SizeY_mm: 0.8; Value2: 50V; SizeArea_mm2: 1.28; AEC Category: Q200
D1 = CMP-0079597-2: Diode, Switching, 75 V, 0.15 A, AEC-Q101, SOD-323; Manufacturer: Diodes Inc.; SizeX_mm: 2.7; Vf_V: 1.25V; AEC Qualified: Y; SizeArea_mm2: 3.645; AEC Category: Q101; SizeAreaWB_mm2: 8.695; Io_A: 150mA; SizeZ_mm: 1; Value1: 0.15A; SizeY_mm: 1.35; TJmax_C: 150°C; Vr_V: 75V; Value: 75V
D2 = CMP-0029023-2: Diode, Superfast Rectifier, SMA; TJmax_C: 150°C; SizeX_mm: 5.59; Green_REACh: Incomplete; SizeAreaWB_mm2: 37.3428; Green_Lifecycle: Not Set; SizeZ_mm: 2.87; SizeArea_mm2: 16.3228; SizeY_mm: 2.92
D3 = CMP-0028759-3: Diode, Schottky, 100 V, 20 A, DDPAK; Manufacturer: ON Semiconductor; Green_REACh: Incomplete; SizeArea_mm2: 154.8892; SizeX_mm: 15.245; SizeZ_mm: 4.445; SizeAreaWB_mm2: 209.6992; Green_Lifecycle: Not Set; TJmax_C: 175°C; Value2: 0.8V; Value: 100V; SizeY_mm: 10.16; Vf_V: 800mV; AEC Category: Q101; AEC Qualified: N; RJC_CperW: 2; Value1: 20A
D4 = CMP-0005614-1: Diode, Zener, 75 V, 550 mW, SMB; Manufacturer: ON Semiconductor; Power_W: 550mW; SizeAreaWB_mm2: 44.156; Value1: 0.55W; RJA_CperW: 226; U/M: EA; SizeZ_mm: 2.6; SizeX_mm: 5.6; SizeY_mm: 3.81; SizeArea_mm2: 21.336; AEC Category: Q101
HT1 = CMP-0074837-1: IEC 61010-1 Hot Surface Warning; SymbolCreator: a0412235
J1-J4 = CMP-0054951-1: Header, 100mil, 3x1, Tin, TH; Manufacturer: TE Connectivity; CNHeader: TRUE; Green_Lifecycle: Active; Green_REACh: Passed; CT: FALSE
J5 J11 = CMP-0075408-2: Header, 100mil, 4x2, Gold, TH; Manufacturer: Samtec; Pitch_mm: 2.54; Cert_VDE: N; Gender: Male; Cert_CSA: Y; Voltage_V: 550V; Green_REACh: Passed; Current_A: 6.3A; Green_Lifecycle: Active; Row_Count: 2
J6-J8 = CMP-0054952-1: Header, 100mil, 2x1, Tin, TH; Manufacturer: TE Connectivity; CNHeader: TRUE; Green_Lifecycle: Active; Green_REACh: Passed; CT: FALSE
J9 J10 = CMP-0055471-1: Terminal Block, 5.08 mm, 2x1, TH; Manufacturer: Phoenix Contact; Cert_VDE: Y; CNHeader: FALSE; Current_A: 17.5A; Green_Lifecycle: Not Set; Gender: Female; Cert_CULUS: N; Green_REACh: Incomplete; Voltage_V: 400V; Row_Count: 1; Pitch_mm: 5.08; ContactFinish: Tin; CT: TRUE
L1 = CMP-0003374-1: Ferrite Bead, 600 ohm @ 100 MHz, 3 A, 1210; Manufacturer: Taiyo Yuden; ZTyp@100MHz_Ohm: 600; SizeAreaWB_mm2: 14.7; DCR_ohm: 0.042; Value1: 0.042 ohm; Value: 600 ohm; Imax_A: 3A; SizeZ_mm: 2.8; SizeX_mm: 3.2; SizeY_mm: 2.5; SizeArea_mm2: 8
L2 = CMP-0092596-1: Shielded Power Inductors 1.5 µH 10.2A 10.5mOhm Max Nonstandard; Manufacturer: Coilcraft; Isat: 3.8A; Tolerance_%: 20%; AEC Grade: Grade 1; Self Resonant Frequency: 50MHz; TaMin_C: -40°C; Value: 1.5uH; Test Frequency: 1MHz; Material: Composite; DCR_ohm: 0.0105; TaMax_C: +125°C; AEC Qualified: Yes; SizeZ_mm: 3.1mm; Ind_H: 1.5µH; Shrouded: true
L3 = CMP-0043075-1: 1.8 µH Shielded Molded Inductor; Manufacturer: Coilcraft; AEC Grade: Grade 1; AEC Qualified: Yes; DCR_ohm: 4.3m; Ind_H: 2.2µH; Irms: 19.7A; Isat: 8.4A; Material: Composite; SizeZ_mm: 6.1mm; Self Resonant Frequency: 35MHz; Shrouded: true; TaMax_C: +125°C; TaMin_C: -40°C; Test Frequency: 1MHz; Tolerance_%: 20%
Q1 = CMP-0000139-1: short; Alternate Manufacturer: None; Manufacturer: Infineon Technologies; SizeZ_mm: 2.29; ChType: P; Value2: 47 nC; Value1: 0.2; VdsMax_V: -100V; SizeX_mm: 9.91; SizeY_mm: 6.54; Vgs_V: -20V; CompType: MOSFET; AEC Qualified: Y; Rdson45_ohm: 0.27; SizeArea_mm2: 64.8114; AEC Category: Q101; IdsMax_A: -15A; SizeAreaWB_mm2: 101.7114; U/M: EA; QgTyp_nC: 47
Q2 Q3 = CMP-0090058-1: N-Channel 80V 126A (Tc) 125W (Tc) Surface Mount 8-PQFN (5x6), Power56; Manufacturer: ON Semiconductor; Number Of N Channels: 1; Threshold Vgs Max: 4V; Reverse Recovery Time: 26ns; Turn Off Delay Time: 25ns; Rdson45_ohm: 3.4m; Input Capacitace At Vds: 3035pF @ 40V; Transconductance: 98S; ChMode: False; Typ Forward Diode Voltage: 0.7V; SizeZ_mm: 1.1mm; Standoff Height: 0mm; Turn On Delay Time: 17ns; Threshold Vgs Min: 2V; Power_W: 2.5W; AEC Qualified: No; Pulse Drain Current: 637A; Reverse Recovery Charge: 48nC; VdsMax_V: 1.2V; TJmax_C: +150°C; Vgs_V: 20V; QgTyp_nC: 39nC @ 10V; Rthja Max: 50°C/W
Q4 = CMP-0000366-2: Transistor, PNP, 100 V, 0.2 A, SOT-23; Manufacturer: Fairchild Semiconductor; TaMax_C: 150°C; Value1: 0.2 A; Vcesat1_V: 250mV; SizeX_mm: 2.5; SizeY_mm: 3; TaMin_C: -55°C; IcRated_A: 200mA; CompType: BJT; SizeZ_mm: 1.1; AEC Qualified: N; Value: 100 V; SizeArea_mm2: 7.5; NPN: 0; Vceo_V: 100V; PNP: 1; AEC Category: Q101; SizeAreaWB_mm2: 14; U/M: EA
R1 R2 R11 R12 R14 R15 R18 R19 R31-R33 R41 R43 R45 R50 R51 R53 R55 R64 = CMP-0023343-3: RES, 0, 1%, 0.1 W, AEC-Q200 Grade 0, 0603; Manufacturer: Stackpole Electronics Inc; Power_W: 100mW; TempCo: ppm/C; U/M: EA; Value: 0; SizeX_mm: 1.6; SizeY_mm: 0.8; SizeZ_mm: 1; Value2: 0.1W; SizeArea_mm2: 1.28; AEC Qualified: Y; AEC Category: Q200
R3 R16 R17 R47 R62 R63 R65 R67 R69 R71 R72 = CMP-0023343-3: DNP; Manufacturer: Stackpole Electronics Inc; Power_W: 100mW; TempCo: ppm/C; Value_Code: 0; Value1: 1%; U/M: EA; SizeX_mm: 1.6; SizeY_mm: 0.8; SizeZ_mm: 1; Value2: 0.1W; SizeArea_mm2: 1.28; AEC Qualified: Y; AEC Category: Q200
R4 = CMP-0022581-4: RES, 71.5 k, 1%, 0.1 W, AEC-Q200 Grade 0, 0603; Manufacturer: Vishay-Dale; Power_W: 100mW; TempCo: 100 ppm/C; Value_Code: 71k5; Value: 71.5k; EIA_Code: E96; SizeX_mm: 1.6; SizeY_mm: 0.8; SizeZ_mm: 1; Value2: 0.1W; SizeArea_mm2: 1.28; AEC Qualified: Y; VDC_V: 75V; AEC Category: Q200; AEC Grade: 0
R5 R6 R22 R23 R30 R35 R38 = CMP-0021990-1: RES, 100 k, 1%, 0.1 W, 0603; Manufacturer: Vishay-Dale; Power_W: 100mW; TempCo: 100 ppm/C; U/M: EA; Value: 100k; EIA_Code: E96; SizeX_mm: 1.6; SizeY_mm: 0.8; SizeZ_mm: 1; Value2: 0.1W; SizeArea_mm2: 1.28; VDC_V: 75V; AEC Category: Q200
R7#1 = CMP-0022358-1: RES, 374 k, 1%, 0.1 W, 0603; Manufacturer: Vishay-Dale; Power_W: 100mW; TempCo: 100 ppm/C; U/M: EA; Value: 374k; EIA_Code: E96; SizeX_mm: 1.6; SizeY_mm: 0.8; SizeZ_mm: 1; Value2: 0.1W; SizeArea_mm2: 1.28; VDC_V: 75V; AEC Category: Q200
R7#2 R8 R10 R13 R20 R39 R54 R60 = CMP-0021998-4: RES, 10.0 k, 1%, 0.1 W, AEC-Q200 Grade 0, 0603; Manufacturer: Vishay-Dale; Power_W: 100mW; TempCo: 100 ppm/C; Value_Code: 10k0; Value: 10.0k; EIA_Code: E96; Res_ohm: 10k; SizeX_mm: 1.6; SizeY_mm: 0.8; SizeZ_mm: 1; Value2: 0.1W; SizeArea_mm2: 1.28; AEC Qualified: Y; VDC_V: 75V; AEC Category: Q200; AEC Grade: 0
R9 = CMP-0023343-3: RES, 0, 1%, 0.1 W, AEC-Q200 Grade 0, 0603; Manufacturer: Stackpole Electronics Inc; Power_W: 100mW; TempCo: ppm/C; Value_Code: 0; U/M: EA; Value: TBD; SizeX_mm: 1.6; SizeY_mm: 0.8; SizeZ_mm: 1; Value2: 0.1W; SizeArea_mm2: 1.28; AEC Qualified: Y; AEC Category: Q200
R24 R28 R29 R36 R40 = CMP-0089632-1: 0 Ohms Jumper 0.125W, 1/8W Chip Resistor 0805 (2012 Metric) Automotive AEC-Q200 Thick Film; Manufacturer: Stackpole Electronics; TempCo: 200ppm/°C; SizeZ_mm: 0.65mm; AEC Grade: Grade 0; AEC Qualified: Yes; Power_W: 125mW; VDC_V: 150V
R25 R26 R37 = CMP-0023343-3: Manufacturer: Stackpole Electronics Inc; Power_W: 100mW; TempCo: ppm/C; Value_Code: 0; Value1: 1%; U/M: EA; SizeX_mm: 1.6; SizeY_mm: 0.8; SizeZ_mm: 1; Value2: 0.1W; SizeArea_mm2: 1.28; AEC Qualified: Y; AEC Category: Q200
R27 = CMP-0020835-1: RES, 100, 1%, 0.125 W, 0805; Manufacturer: Vishay-Dale; Power_W: 125mW; TempCo: 100 ppm/C; Value_Code: 100R; U/M: EA; Value: 100; EIA_Code: E96; SizeX_mm: 2; SizeY_mm: 1.25; SizeZ_mm: 1.45; Value2: 0.125W; SizeArea_mm2: 2.5; VDC_V: 150V; AEC Category: Q200
R34 = CMP-0022377-4: RES, 3.48 k, 1%, 0.1 W, AEC-Q200 Grade 0, 0603; Manufacturer: Vishay-Dale; Power_W: 100mW; TempCo: 100 ppm/C; Value_Code: 3k48; Value: 3.48k; EIA_Code: E96; SizeX_mm: 1.6; SizeY_mm: 0.8; SizeZ_mm: 1; Value2: 0.1W; SizeArea_mm2: 1.28; AEC Qualified: Y; VDC_V: 75V; AEC Category: Q200; AEC Grade: 0
R42 = CMP-0022024-4: RES, 121 k, 1%, 0.1 W, AEC-Q200 Grade 0, 0603; Manufacturer: Vishay-Dale; Power_W: 100mW; TempCo: 100 ppm/C; Value: 121k; EIA_Code: E96; SizeX_mm: 1.6; SizeY_mm: 0.8; SizeZ_mm: 1; Value2: 0.1W; SizeArea_mm2: 1.28; AEC Qualified: Y; VDC_V: 75V; AEC Category: Q200; AEC Grade: 0
R44 R46 R49 R103 = CMP-0094724-1: Jumper 0.25W, 1/4W Chip Resistor 1206 (3216 Metric) - Thick Film; Manufacturer: Vishay; SizeZ_mm: 0.65mm; Power_W: 250mW; VDC_V: 200V; AEC Qualified: No
R48 = CMP-0018318-2: RES, 47.0 k, 1%, 0.25 W, 1206; Manufacturer: Yageo America; Power_W: 250mW; TempCo: 100 ppm/C; Value_Code: 47k0; U/M: EA; Value: 47.0k; Res_ohm: 47k; SizeX_mm: 3.2; SizeY_mm: 1.6; SizeZ_mm: 1.35; Value2: 0.25W; SizeArea_mm2: 5.12; VDC_V: 200V; AEC Category: Q200
R52 = CMP-0020797-2: RES, 1.0, 5%, 0.4 W, AEC-Q200 Grade 0, 0805; Manufacturer: Rohm; Power_W: 400mW; TempCo: 200 ppm/C; Value_Code: 1R00; U/M: EA; Value: 1.0; EIA_Code: E24; Res_ohm: 1; SizeX_mm: 2; SizeY_mm: 1.25; SizeZ_mm: 1.45; Value2: 0.4W; SizeArea_mm2: 2.5; AEC Qualified: Y; AEC Grade: 0; AEC Category: Q200
R56 = CMP-0022204-1: RES, 20.0 k, 1%, 0.1 W, 0603; Manufacturer: Vishay-Dale; Power_W: 100mW; TempCo: 100 ppm/C; Value_Code: 20k0; U/M: EA; Value: 20.0k; EIA_Code: E96; Res_ohm: 20k; SizeX_mm: 1.6; SizeY_mm: 0.8; SizeZ_mm: 1; Value2: 0.1W; SizeArea_mm2: 1.28; VDC_V: 75V; AEC Category: Q200
R57 = CMP-0022109-2: RES, 1.00 k, 1%, 0.1 W, 0603; Manufacturer: Vishay-Dale; Power_W: 100mW; TempCo: 100 ppm/C; Value_Code: 1k00; U/M: EA; Value: 1.00k; EIA_Code: E96; Res_ohm: 1k; SizeX_mm: 1.6; SizeY_mm: 0.8; SizeZ_mm: 1; Value2: 0.1W; SizeArea_mm2: 1.28; VDC_V: 75V; AEC Category: Q200
R58 = CMP-0018576-1: RES, 10 k, 5%, 0.25 W, 1206; Manufacturer: Vishay-Dale; Power_W: 250mW; TempCo: 200 ppm/C; Value_Code: 10k0; U/M: EA; Value: 10k; EIA_Code: E24; SizeX_mm: 3.2; SizeY_mm: 1.6; SizeZ_mm: 1.35; Value2: 0.25W; SizeArea_mm2: 5.12; VDC_V: 200V; AEC Category: Q200
R59 = CMP-0022447-3: RES, 49.9 k, 1%, 0.1 W, 0603; Manufacturer: Vishay-Dale; Power_W: 100mW; TempCo: 100 ppm/C; Value_Code: 49k9; U/M: EA; Value: 49.9k; EIA_Code: E96; SizeX_mm: 1.6; SizeY_mm: 0.8; SizeZ_mm: 1; Value2: 0.1W; SizeArea_mm2: 1.28; VDC_V: 75V; AEC Category: Q200
R61 = CMP-0080492-1: RES, 49.9, 1%, 0.1 W, 0603; Manufacturer: TT Electronics/IRC; Power_W: 100mW; TempCo: 100 ppm/C; SizeAreaWB_mm2: 4.68; Value_Code: 49R9; Value: 49.9; EIA_Code: E96; SizeX_mm: 1.6; SizeY_mm: 0.8; SizeZ_mm: 1; Value2: 0.1W; SizeArea_mm2: 1.28; AEC Qualified: N; AEC Category: Q200
R66 = CMP-0022458-1: RES, 4.99 k, 1%, 0.1 W, 0603; Manufacturer: Vishay-Dale; Power_W: 100mW; TempCo: 100 ppm/C; Value_Code: 4k99; U/M: EA; Value: 4.99k; EIA_Code: E96; SizeX_mm: 1.6; SizeY_mm: 0.8; SizeZ_mm: 1; Value2: 0.1W; SizeArea_mm2: 1.28; VDC_V: 75V; AEC Category: Q200
R68 = CMP-0023343-3: RES, 0, 1%, 0.1 W, AEC-Q200 Grade 0, 0603; Manufacturer: Stackpole Electronics Inc; PartNumber: RMCF0603ZT0R00; Power_W: 100mW; TempCo: ppm/C; U/M: EA; Value: 0; SizeX_mm: 1.6; SizeY_mm: 0.8; SizeZ_mm: 1; Value2: 0.1W; SizeArea_mm2: 1.28; CompType: Resistor; AEC Qualified: Y; AEC Category: Q200
R70 = CMP-0022068-3: RES, 15.8 k, 1%, 0.1 W, 0603; Manufacturer: Vishay-Dale; Power_W: 100mW; TempCo: 100 ppm/C; Value_Code: 15k8; U/M: EA; Value: 15.8k; EIA_Code: E96; SizeX_mm: 1.6; SizeY_mm: 0.8; SizeZ_mm: 1; Value2: 0.1W; SizeArea_mm2: 1.28; VDC_V: 75V; AEC Category: Q200
R101 R102 = CMP-0023345-1: RES, 2.00 k, 1%, 0.1 W, 0603; Manufacturer: Vishay Foil Resistors; Power_W: 100mW; TempCo: 0.2 ppm/C; Value_Code: 2k00; U/M: EA; Value: 2.00k; EIA_Code: E96; Res_ohm: 2k; SizeX_mm: 1.6; SizeY_mm: 0.81; SizeZ_mm: 0.64; Value2: 0.1W; SizeArea_mm2: 1.296; AEC Qualified: N; VDC_V: 20V; AEC Category: Q200
TP1-TP4 TP8-TP13 = CMP-0055140-1: Test Point, Miniature, Orange, TH; Manufacturer: Keystone; CNHeader: FALSE; Green_Lifecycle: Active; Green_REACh: Passed; ContactFinish: Silver; CT: TRUE
TP5-TP7 TP14-TP18 = CMP-0055141-1: Test Point, Miniature, Yellow, TH; Manufacturer: Keystone; CNHeader: FALSE; Green_Lifecycle: Active; Green_REACh: Passed; ContactFinish: Silver; CT: TRUE
TP19 TP38 = CMP-0055148-2: Test Point, Multipurpose, Black, TH; PartNumber: 5011; Manufacturer: Keystone Electronics; CNHeader: FALSE; ContactFinish: Silver; Green_REACh: Passed; Green_Lifecycle: Active; CT: TRUE
TP20-TP34 TP36 TP37 TP39 TP40 TP42 TP43 = CMP-0055137-2: Test Point, Miniature, Red, TH; Manufacturer: Keystone Electronics; Green_REACh: Passed; Green_Lifecycle: Active; ContactFinish: Silver; CNHeader: FALSE; CT: TRUE
TP35 TP41 = CMP-0055138-2: Test Point, Miniature, Black, TH; Manufacturer: Keystone Electronics; ContactFinish: Silver; CNHeader: FALSE; Green_Lifecycle: Active; Green_REACh: Passed; CT: TRUE
U1 U2 = CMP-0098319-1: Wide VIN 65 V Dual Channel Overvoltage & Undervoltage (OV & UV) TPS3762D02OVDDFR; Manufacturer: Texas Instruments; SizeZ_mm: 1.1mm; AEC Qualified: Yes; AEC Grade: Grade 1; Max Supply Voltage: 65V; Min Supply Voltage: 2.7V; Nominal Supply Current: 8.1-31.1uA; Number Of Outputs: 1; Reset Type: Active Low; Standoff Height: 0mm; TaMax_C: +150°C; TaMin_C: -40°C; TJmax_C: +125°C
U3 = CMP-0089212-1: Ideal Diode Controller with Load Dump Protection; Manufacturer: Texas Instruments; Number Of Outputs: 1; TJmax_C: +150°C; Standoff Height: 0mm; AEC Qualified: Yes; Max Supply Voltage: 65V; TaMin_C: -40°C; SizeZ_mm: 0.8mm; TaMax_C: +125°C; Nominal Supply Current: 428uA; AEC Grade: Grade 1; Min Supply Voltage: 3V
U4 = CMP-0096221-1: 3.5V to 65V Synchronous Step-Down Voltage Regulator; Manufacturer: Texas Instruments; Switching Topology: Buck; Number Of Outputs: 1; AEC Qualified: Yes; Standoff Height: 0mm; Output Type: AdjustableProgrammable; SizeZ_mm: 0.7mm
x1 = CMP-0074769-1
